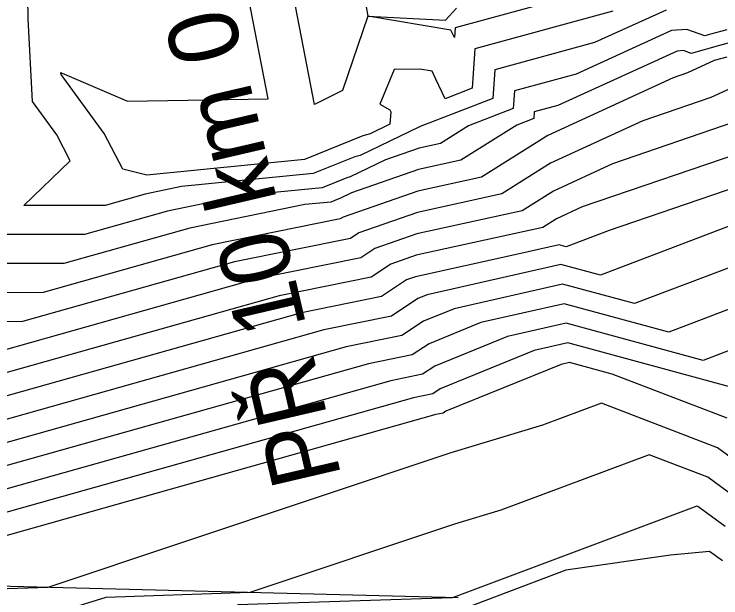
# Model space of a CAD drawing. Extents: x -549394 to -546608, y -1037055 to -1033629.
# Drawn here: x -548165.9 to -548073.8, y -1035710.4 to -1035634.3 of the extents above; entities that cross this region are included whole.
import ezdxf

# ---------------------------------------------------------------- set-up
doc = ezdxf.new("R2010")
doc.units = 0
for name, color, linetype in [('hlavni_vrst', 7, 'Continuous'), ('hrana_L', 7, 'Continuous'), ('norm_vrst', 7, 'Continuous'), ('x_popis_pricne_rezy_C1', 7, 'Continuous')]:
    doc.layers.add(name, color=color, linetype=linetype)

msp = doc.modelspace()

# ---------------------------------------------------------------- linework, layer by layer
at = {"layer": 'hlavni_vrst'}
for p, q in [((-548126.762, -1035646.052), (-548129.952, -1035629.626)), ((-548085.493, -1035629.786), (-548108.416, -1035636.051)), ((-548120.598, -1035630.037), (-548119.82, -1035634.51)), ((-548109.672, -1035635.051), (-548108.228, -1035633.502)), ((-548119.82, -1035634.51), (-548123.127, -1035644.224)), ((-548119.82, -1035634.51), (-548109.672, -1035635.051)), ((-548108.972, -1035636.341), (-548119.82, -1035634.51)), ((-548119.82, -1035634.51), (-548119.82, -1035634.51)), ((-548119.82, -1035634.51), (-548119.82, -1035634.51)), ((-548108.503, -1035637.315), (-548108.972, -1035636.341)), ((-548108.416, -1035636.051), (-548108.503, -1035637.315)), ((-548072.978, -1035639.863), (-548074.624, -1035640.325)), ((-548074.624, -1035640.325), (-548078.114, -1035641.921)), ((-548078.114, -1035641.921), (-548079.996, -1035642.566)), ((-548079.996, -1035642.566), (-548096.356, -1035650.088)), ((-548123.127, -1035644.224), (-548126.762, -1035646.052)), ((-548096.356, -1035650.088), (-548105.007, -1035655.512)), ((-548105.007, -1035655.512), (-548113.271, -1035657.329)), ((-548113.271, -1035657.329), (-548123.035, -1035660.724)), ((-548063.853, -1035658.546), (-548089.476, -1035668.309)), ((-548123.406, -1035660.972), (-548140.112, -1035664.365)), ((-548123.035, -1035660.724), (-548123.406, -1035660.972)), ((-548140.112, -1035664.365), (-548162.155, -1035670.572)), ((-548094.643, -1035666.911), (-548112.051, -1035670.858)), ((-548089.476, -1035668.309), (-548094.643, -1035666.911)), ((-548162.155, -1035670.572), (-548184.683, -1035670.623)), ((-548113.29, -1035671.362), (-548116.702, -1035673.633)), ((-548112.051, -1035670.858), (-548113.29, -1035671.362)), ((-548116.702, -1035673.633), (-548125.535, -1035675.428)), ((-548125.535, -1035675.428), (-548175.621, -1035689.532)), ((-548093.507, -1035679.7), (-548094.616, -1035679.952)), ((-548087.95, -1035681.205), (-548093.507, -1035679.7)), ((-548094.616, -1035679.952), (-548109.627, -1035686.048)), ((-548072.951, -1035686.967), (-548087.95, -1035681.205)), ((-548109.627, -1035686.048), (-548109.998, -1035686.295)), ((-548110.958, -1035686.49), (-548184.069, -1035707.078)), ((-548109.998, -1035686.295), (-548110.958, -1035686.49))]:
    msp.add_line(p, q, dxfattribs=at)
at = {"layer": 'hrana_L'}
msp.add_line((-548108.04, -1035710.38), (-548188.98, -1035708.34), dxfattribs=at)
at = {"layer": 'norm_vrst'}
for p, q in [((-548164.107, -1035634.874), (-548164.307, -1035623.897)), ((-548132.798, -1035645.298), (-548136.207, -1035627.741)), ((-548087.875, -1035633.882), (-548105.837, -1035638.791)), ((-548080.922, -1035633.732), (-548090.258, -1035637.978)), ((-548163.551, -1035645.671), (-548164.107, -1035634.874)), ((-548080.192, -1035636.413), (-548092.64, -1035642.074)), ((-548078.206, -1035636.249), (-548080.192, -1035636.413)), ((-548075.871, -1035637.08), (-548078.206, -1035636.249)), ((-548073.001, -1035636.296), (-548074.937, -1035636.818)), ((-548066.328, -1035636.283), (-548073.957, -1035638.34)), ((-548074.937, -1035636.818), (-548075.871, -1035637.08)), ((-548090.258, -1035637.978), (-548103.258, -1035641.531)), ((-548105.837, -1035638.791), (-548106.191, -1035643.929)), ((-548079.463, -1035639.093), (-548095.023, -1035646.17)), ((-548078.624, -1035639.024), (-548079.463, -1035639.093)), ((-548077.639, -1035639.375), (-548078.624, -1035639.024)), ((-548073.957, -1035638.34), (-548077.639, -1035639.375)), ((-548159.823, -1035642.019), (-548159.826, -1035641.863)), ((-548159.826, -1035641.863), (-548159.773, -1035642)), ((-548159.773, -1035642), (-548159.673, -1035641.968)), ((-548159.673, -1035641.968), (-548151.158, -1035645.624)), ((-548116.381, -1035641.471), (-548118.225, -1035646.003)), ((-548113.017, -1035641.45), (-548116.381, -1035641.471)), ((-548111.44, -1035641.716), (-548113.017, -1035641.45)), ((-548110.945, -1035642.746), (-548111.44, -1035641.716)), ((-548103.258, -1035641.531), (-548103.514, -1035645.25)), ((-548159.817, -1035642.125), (-548159.823, -1035642.019)), ((-548154.178, -1035649.827), (-548159.817, -1035642.125)), ((-548109.738, -1035645.305), (-548110.945, -1035642.746)), ((-548092.64, -1035642.074), (-548100.678, -1035644.271)), ((-548071.107, -1035643.324), (-548075.093, -1035645.146)), ((-548106.191, -1035643.929), (-548109.738, -1035645.305)), ((-548100.678, -1035644.271), (-548100.837, -1035646.571)), ((-548160.385, -1035649.995), (-548163.551, -1035645.671)), ((-548151.158, -1035645.624), (-548132.798, -1035645.298)), ((-548103.514, -1035645.25), (-548112.977, -1035648.919)), ((-548075.093, -1035645.146), (-548083.944, -1035648.181)), ((-548118.225, -1035646.003), (-548116.953, -1035646.728)), ((-548100.837, -1035646.571), (-548106.688, -1035648.839)), ((-548095.023, -1035646.17), (-548098.099, -1035647.011)), ((-548116.953, -1035646.728), (-548116.801, -1035646.987)), ((-548116.801, -1035646.987), (-548116.933, -1035648.632)), ((-548098.099, -1035647.011), (-548098.16, -1035647.891)), ((-548098.16, -1035647.891), (-548100.399, -1035648.76)), ((-548083.944, -1035648.181), (-548095.976, -1035653.713)), ((-548072.071, -1035648.372), (-548087.892, -1035653.796)), ((-548113.084, -1035648.963), (-548120.818, -1035652.679)), ((-548116.933, -1035648.632), (-548119.504, -1035649.868)), ((-548113.041, -1035648.948), (-548113.084, -1035648.963)), ((-548113.013, -1035648.942), (-548113.041, -1035648.948)), ((-548112.977, -1035648.919), (-548113.013, -1035648.942)), ((-548106.688, -1035648.839), (-548110.345, -1035651.132)), ((-548100.399, -1035648.76), (-548107.676, -1035653.322)), ((-548158.623, -1035653.372), (-548160.385, -1035649.995)), ((-548151.744, -1035654.492), (-548154.178, -1035649.827)), ((-548120.482, -1035650.14), (-548128.064, -1035653.201)), ((-548119.504, -1035649.868), (-548120.482, -1035650.14)), ((-548110.345, -1035651.132), (-548113.117, -1035651.742)), ((-548113.117, -1035651.742), (-548117.504, -1035653.267)), ((-548069.049, -1035651.597), (-548091.84, -1035659.41)), ((-548121.516, -1035652.873), (-548126.925, -1035655.058)), ((-548120.818, -1035652.679), (-548121.516, -1035652.873)), ((-548164.675, -1035659.22), (-548158.623, -1035653.372)), ((-548128.064, -1035653.201), (-548148.648, -1035655.242)), ((-548117.504, -1035653.267), (-548122.132, -1035655.491)), ((-548107.676, -1035653.322), (-548113.194, -1035654.535)), ((-548095.976, -1035653.713), (-548102.339, -1035657.702)), ((-548087.892, -1035653.796), (-548095.596, -1035657.338)), ((-548148.648, -1035655.242), (-548151.744, -1035654.492)), ((-548113.194, -1035654.535), (-548121.924, -1035657.571)), ((-548066.028, -1035654.823), (-548088.341, -1035662.472)), ((-548126.925, -1035655.058), (-548144.097, -1035656.76)), ((-548122.549, -1035655.607), (-548125.786, -1035656.914)), ((-548122.132, -1035655.491), (-548122.549, -1035655.607)), ((-548144.097, -1035656.76), (-548148.859, -1035657.728)), ((-548125.786, -1035656.914), (-548136.062, -1035657.933)), ((-548121.924, -1035657.571), (-548123.446, -1035658.302)), ((-548095.596, -1035657.338), (-548099.67, -1035659.892)), ((-548148.859, -1035657.728), (-548154.075, -1035659.197)), ((-548136.062, -1035657.933), (-548145.943, -1035659.94)), ((-548123.583, -1035658.341), (-548124.648, -1035658.77)), ((-548123.446, -1035658.302), (-548123.583, -1035658.341)), ((-548102.339, -1035657.702), (-548113.348, -1035660.123)), ((-548154.075, -1035659.197), (-548164.675, -1035659.22)), ((-548128.027, -1035659.105), (-548143.028, -1035662.153)), ((-548124.648, -1035658.77), (-548128.027, -1035659.105)), ((-548091.84, -1035659.41), (-548095.216, -1035660.963)), ((-548145.943, -1035659.94), (-548156.768, -1035662.988)), ((-548113.348, -1035660.123), (-548120.966, -1035662.772)), ((-548099.67, -1035659.892), (-548113.424, -1035662.916)), ((-548095.216, -1035660.963), (-548097.002, -1035662.082)), ((-548143.028, -1035662.153), (-548159.461, -1035666.78)), ((-548097.002, -1035662.082), (-548113.501, -1035665.71)), ((-548156.768, -1035662.988), (-548178.766, -1035663.038)), ((-548120.966, -1035662.772), (-548122.065, -1035663.504)), ((-548113.424, -1035662.916), (-548118.896, -1035664.819)), ((-548088.341, -1035662.472), (-548093.938, -1035664.605)), ((-548122.065, -1035663.504), (-548137.197, -1035666.578)), ((-548118.896, -1035664.819), (-548120.725, -1035666.036)), ((-548094.87, -1035664.353), (-548100.263, -1035665.576)), ((-548093.938, -1035664.605), (-548094.87, -1035664.353)), ((-548065.812, -1035664.697), (-548085.013, -1035672.014)), ((-548113.501, -1035665.71), (-548116.827, -1035666.866)), ((-548100.263, -1035665.576), (-548113.578, -1035668.503)), ((-548159.461, -1035666.78), (-548184.252, -1035666.836)), ((-548137.197, -1035666.578), (-548164.848, -1035674.364)), ((-548120.725, -1035666.036), (-548134.282, -1035668.79)), ((-548116.827, -1035666.866), (-548119.384, -1035668.569)), ((-548119.384, -1035668.569), (-548131.366, -1035671.003)), ((-548113.578, -1035668.503), (-548114.758, -1035668.914)), ((-548134.282, -1035668.79), (-548167.541, -1035678.156)), ((-548114.758, -1035668.914), (-548118.043, -1035671.101)), ((-548094.416, -1035669.469), (-548108.564, -1035672.677)), ((-548085.013, -1035672.014), (-548094.416, -1035669.469)), ((-548131.366, -1035671.003), (-548170.235, -1035681.948)), ((-548118.043, -1035671.101), (-548128.451, -1035673.215)), ((-548067.771, -1035670.849), (-548080.551, -1035675.718)), ((-548094.189, -1035672.027), (-548105.077, -1035674.496)), ((-548080.551, -1035675.718), (-548094.189, -1035672.027)), ((-548128.451, -1035673.215), (-548172.928, -1035685.74)), ((-548108.564, -1035672.677), (-548112.558, -1035674.299)), ((-548164.848, -1035674.364), (-548185.115, -1035674.41)), ((-548112.558, -1035674.299), (-548115.361, -1035676.166)), ((-548105.077, -1035674.496), (-548111.825, -1035677.236)), ((-548093.961, -1035674.584), (-548101.59, -1035676.314)), ((-548076.088, -1035679.423), (-548093.961, -1035674.584)), ((-548115.361, -1035676.166), (-548122.62, -1035677.64)), ((-548101.59, -1035676.314), (-548111.092, -1035680.174)), ((-548069.73, -1035677), (-548076.088, -1035679.423)), ((-548122.62, -1035677.64), (-548178.315, -1035693.324)), ((-548111.825, -1035677.236), (-548114.02, -1035678.698)), ((-548093.734, -1035677.142), (-548098.103, -1035678.133)), ((-548071.831, -1035683.071), (-548093.734, -1035677.142)), ((-548114.02, -1035678.698), (-548119.705, -1035679.853)), ((-548098.103, -1035678.133), (-548110.36, -1035683.111)), ((-548119.705, -1035679.853), (-548181.008, -1035697.116)), ((-548111.092, -1035680.174), (-548112.68, -1035681.231)), ((-548112.68, -1035681.231), (-548116.789, -1035682.065)), ((-548116.789, -1035682.065), (-548183.701, -1035700.908)), ((-548110.36, -1035683.111), (-548111.339, -1035683.763)), ((-548113.874, -1035684.278), (-548186.394, -1035704.7)), ((-548111.339, -1035683.763), (-548113.874, -1035684.278)), ((-548089.33, -1035685), (-548097.015, -1035687.884)), ((-548074.219, -1035690.806), (-548089.33, -1035685)), ((-548097.015, -1035687.884), (-548108.996, -1035691.472)), ((-548072.435, -1035692.104), (-548074.219, -1035690.806)), ((-548108.996, -1035691.472), (-548161.561, -1035709.031)), ((-548083.117, -1035691.713), (-548102.446, -1035698.966)), ((-548075.487, -1035694.645), (-548083.117, -1035691.713)), ((-548072.815, -1035696.589), (-548075.487, -1035694.645)), ((-548102.446, -1035698.966), (-548108.525, -1035700.787)), ((-548076.904, -1035698.426), (-548107.877, -1035710.048)), ((-548076.755, -1035698.483), (-548076.904, -1035698.426)), ((-548073.196, -1035701.073), (-548076.755, -1035698.483)), ((-548108.525, -1035700.787), (-548135.196, -1035709.696)), ((-548075.238, -1035704.349), (-548080.344, -1035704.801)), ((-548073.577, -1035705.558), (-548075.238, -1035704.349)), ((-548080.344, -1035704.801), (-548093.976, -1035706.787)), ((-548093.976, -1035706.787), (-548107.427, -1035711.866)), ((-548161.561, -1035709.031), (-548171.135, -1035709.354)), ((-548135.196, -1035709.696), (-548153.976, -1035710.329)), ((-548108.054, -1035710.101), (-548108.831, -1035710.36)), ((-548107.877, -1035710.048), (-548108.054, -1035710.101)), ((-548153.976, -1035710.329), (-548159.318, -1035711.983)), ((-548108.831, -1035710.36), (-548136.817, -1035711.304))]:
    msp.add_line(p, q, dxfattribs=at)

# ---------------------------------------------------------------- texts
at = {"layer": 'x_popis_pricne_rezy_C1'}
msp.add_text('PŘ 10 km 0.9000', height=9.06272, rotation=103.11024, dxfattribs=at).set_placement((-548123.22, -1035694.626))

doc.saveas('drawing.dxf')
